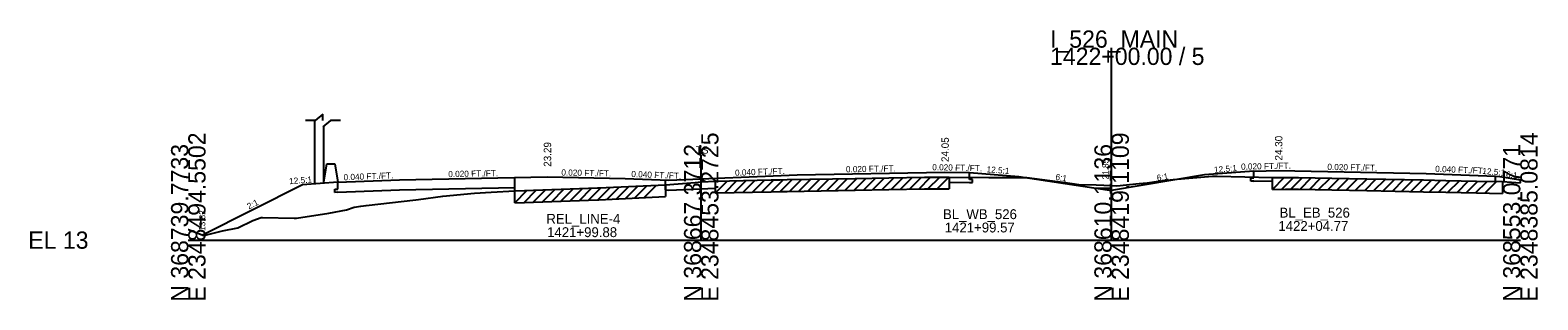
# Model space of a CAD drawing. Extents: x -170 to 2527928, y -10 to 1619750.
# Drawn here: x 3974.3 to 4219.3, y 1990.3 to 2034.1 of the extents above; entities that cross this region are included whole.
import ezdxf

# ---------------------------------------------------------------- set-up
doc = ezdxf.new("R2010")
doc.units = 0
for name, color, linetype in [('Default', 7, 'Continuous'), ('RD_GPK_XS_Cell', 7, 'Continuous'), ('RD_PD_NOISE-WALL-GM', 7, 'Continuous'), ('RD_XS_Base', 7, 'Continuous'), ('RD_XS_EarthShd', 7, 'Continuous'), ('RD_XS_ExGround', 7, 'Continuous'), ('RD_XS_ExPaveRet', 7, 'Continuous'), ('RD_XS_MatchLine', 7, 'Continuous'), ('RD_XS_Pave', 7, 'Continuous'), ('RD_XS_PaveShd', 7, 'Continuous'), ('RD_XS_TieSlope', 7, 'Continuous'), ('RD_XS_TX_Elev_EX', 7, 'Continuous'), ('RD_XS_TX_Slope', 7, 'Continuous'), ('RD_XS_TX_Station', 7, 'Continuous')]:
    doc.layers.add(name, color=color, linetype=linetype)

msp = doc.modelspace()

# ---------------------------------------------------------------- linework, layer by layer
at = {"layer": 'Default'}
for p, q in [((4020.63, 2019.42), (4019.05, 2019.42)), ((4021.88, 2020.45), (4020.63, 2019.42)), ((4021.88, 2019.42), (4021.88, 2020.45)), ((4023.13, 2019.42), (4021.88, 2018.4)), ((4024.73, 2019.42), (4023.13, 2019.42))]:
    msp.add_line(p, q, dxfattribs=at)
at = {"layer": 'RD_GPK_XS_Cell'}
for p, q in [((4150.02, 2000), (4150.02, 2031.24)), ((4000, 2000), (4083.34, 2000)), ((4083.34, 2000), (4150.02, 2000)), ((4150.02, 2000), (4216.43, 2000))]:
    msp.add_line(p, q, dxfattribs=at)
at = {"layer": 'RD_PD_NOISE-WALL-GM'}
for p, q in [((4020.5, 2019.42), (4020.5, 2009.1)), ((4022, 2009.22), (4022, 2018.5)), ((4022, 2009.41), (4022.49, 2012.41)), ((4022.49, 2012.41), (4023.82, 2012.41)), ((4023.82, 2012.41), (4024.31, 2009.41))]:
    msp.add_line(p, q, dxfattribs=at)
at = {"layer": 'RD_XS_Base'}
for p, q in [((4173.12, 2010.09), (4173.12, 2011.22)), ((4024.31, 2008.27), (4024.31, 2009.41)), ((4053.05, 2008), (4053.05, 2010.18)), ((4077.53, 2008.14), (4077.53, 2009.77)), ((4123.63, 2009.4), (4126.92, 2009.34)), ((4126.92, 2009.84), (4126.92, 2010.97)), ((4127.42, 2009.83), (4126.92, 2009.84)), ((4126.92, 2009.34), (4127.42, 2009.33)), ((4127.42, 2009.33), (4127.42, 2009.83)), ((4172.62, 2010.08), (4173.12, 2010.09)), ((4172.62, 2009.58), (4172.62, 2010.08)), ((4173.12, 2009.59), (4172.62, 2009.58)), ((4173.12, 2009.59), (4176.15, 2009.65)), ((4212.37, 2009.52), (4212.37, 2010.38)), ((4023.81, 2008.25), (4024.31, 2008.27)), ((4023.81, 2007.75), (4023.81, 2008.25)), ((4024.31, 2007.77), (4023.81, 2007.75)), ((4024.31, 2007.77), (4034.31, 2008.17)), ((4034.31, 2008.17), (4053.05, 2008.55)), ((4077.53, 2008.14), (4078.09, 2008.12)), ((4078.09, 2008.12), (4085.68, 2008.42))]:
    msp.add_line(p, q, dxfattribs=at)
at = {"layer": 'RD_XS_EarthShd'}
for p, q in [((4173.12, 2011.22), (4165.12, 2010.58)), ((4018.54, 2008.95), (4002.3, 2000.82)), ((4024.31, 2009.41), (4018.54, 2008.95)), ((4126.92, 2010.97), (4134.92, 2010.33))]:
    msp.add_line(p, q, dxfattribs=at)
at = {"layer": 'RD_XS_ExGround'}
msp.add_lwpolyline([(4000, 2001.75), (4000.04, 2001.74), (4002.52, 2000.74), (4005.56, 2001.5), (4008.03, 2001.99), (4010.48, 2003.18), (4011.82, 2003.65), (4012.08, 2003.65), (4017.23, 2003.54), (4017.31, 2003.55), (4017.58, 2003.58), (4022.84, 2004.39), (4025.69, 2004.93), (4026.96, 2005.35), (4028.05, 2005.5), (4028.92, 2005.61), (4036.95, 2006.53), (4037.4, 2006.57), (4041.36, 2007.13), (4046.51, 2007.6), (4049.21, 2007.77), (4053.05, 2008), (4054.64, 2008.04), (4065, 2008.42), (4066.5, 2008.47), (4066.68, 2008.48), (4077.53, 2008.99), (4082.33, 2009.38), (4083.34, 2009.44), (4085.68, 2009.58), (4094.7, 2009.77), (4096.16, 2009.8), (4097.31, 2009.82), (4108.34, 2010.02), (4113.82, 2010.12), (4119.62, 2010.22), (4121.45, 2010.22), (4123.63, 2010.21), (4130.08, 2010.17), (4136.22, 2010.15), (4142.45, 2009.34), (4143.59, 2009.2), (4144.7, 2009.05), (4147.53, 2008.95), (4150.02, 2008.85), (4150.87, 2008.82), (4154.52, 2009.17), (4155.81, 2009.31), (4157.65, 2009.55), (4160, 2009.83), (4166.43, 2010.41), (4167.16, 2010.4), (4176.15, 2010.16), (4178.29, 2010.18), (4180.36, 2010.19), (4185.8, 2010.07), (4191.49, 2009.97), (4200.7, 2009.78), (4204.31, 2009.7), (4209.32, 2009.57), (4213.53, 2009.5), (4216.43, 2009.3)], dxfattribs=at)
at = {"layer": 'RD_XS_ExPaveRet'}
for p, q in [((4071.05, 2006.77), (4073.06, 2008.78)), ((4072.55, 2006.84), (4074.56, 2008.85)), ((4074.05, 2006.91), (4076.06, 2008.92)), ((4077.53, 2008.99), (4077.53, 2007.07)), ((4085.68, 2007.67), (4087.63, 2009.62)), ((4085.68, 2007.67), (4085.68, 2009.58)), ((4087.18, 2007.7), (4089.13, 2009.66)), ((4088.68, 2007.73), (4090.63, 2009.69)), ((4090.18, 2007.76), (4092.13, 2009.72)), ((4091.68, 2007.79), (4093.63, 2009.75)), ((4093.18, 2007.82), (4095.13, 2009.78)), ((4094.68, 2007.85), (4096.63, 2009.81)), ((4096.18, 2007.89), (4098.13, 2009.84)), ((4097.68, 2007.91), (4099.63, 2009.86)), ((4099.18, 2007.94), (4101.13, 2009.89)), ((4100.68, 2007.97), (4102.63, 2009.92)), ((4102.18, 2007.99), (4104.13, 2009.94)), ((4103.68, 2008.02), (4105.63, 2009.97)), ((4105.18, 2008.05), (4107.13, 2010)), ((4106.68, 2008.07), (4108.63, 2010.02)), ((4108.18, 2008.1), (4110.13, 2010.05)), ((4109.68, 2008.13), (4111.63, 2010.08)), ((4111.18, 2008.15), (4113.13, 2010.1)), ((4112.68, 2008.18), (4114.63, 2010.13)), ((4114.18, 2008.21), (4116.13, 2010.16)), ((4115.68, 2008.23), (4117.63, 2010.19)), ((4117.18, 2008.26), (4119.13, 2010.21)), ((4118.68, 2008.29), (4120.61, 2010.22)), ((4120.18, 2008.31), (4122.09, 2010.22)), ((4121.68, 2008.3), (4123.59, 2010.21)), ((4123.63, 2010.21), (4123.63, 2008.3)), ((4176.15, 2008.24), (4178.08, 2010.18)), ((4176.15, 2008.24), (4176.15, 2010.16)), ((4177.65, 2008.26), (4179.58, 2010.18)), ((4179.15, 2008.27), (4181.05, 2010.17)), ((4180.65, 2008.27), (4182.52, 2010.14)), ((4182.15, 2008.23), (4184.02, 2010.11)), ((4183.65, 2008.2), (4185.52, 2010.08)), ((4185.15, 2008.17), (4187.03, 2010.05)), ((4186.65, 2008.14), (4188.53, 2010.02)), ((4188.15, 2008.11), (4190.03, 2010)), ((4189.65, 2008.09), (4191.53, 2009.97)), ((4191.15, 2008.06), (4193.02, 2009.94)), ((4192.65, 2008.03), (4194.52, 2009.91)), ((4194.15, 2008), (4196.02, 2009.87)), ((4195.65, 2007.97), (4197.52, 2009.84)), ((4197.15, 2007.93), (4199.02, 2009.81)), ((4198.65, 2007.9), (4200.52, 2009.78)), ((4200.15, 2007.87), (4202.02, 2009.75)), ((4201.65, 2007.84), (4203.52, 2009.71)), ((4203.15, 2007.8), (4205.02, 2009.68)), ((4204.65, 2007.77), (4206.52, 2009.64)), ((4206.15, 2007.73), (4208.02, 2009.61)), ((4207.65, 2007.7), (4209.52, 2009.57)), ((4209.15, 2007.66), (4211.03, 2009.54)), ((4210.65, 2007.63), (4212.53, 2009.52)), ((4213.53, 2009.5), (4213.53, 2007.58)), ((4053.05, 2006.08), (4055.02, 2008.06)), ((4053.05, 2006.08), (4053.05, 2008)), ((4054.55, 2006.12), (4056.54, 2008.11)), ((4054.64, 2006.13), (4065, 2006.5)), ((4056.05, 2006.18), (4058.04, 2008.17)), ((4057.55, 2006.23), (4059.54, 2008.22)), ((4059.05, 2006.29), (4061.04, 2008.27)), ((4060.55, 2006.34), (4062.54, 2008.33)), ((4062.05, 2006.39), (4064.04, 2008.38)), ((4063.55, 2006.45), (4065.54, 2008.44)), ((4065, 2006.5), (4066.5, 2006.55)), ((4065.05, 2006.5), (4067.04, 2008.5)), ((4066.5, 2006.55), (4066.68, 2006.56)), ((4066.55, 2006.56), (4068.56, 2008.57)), ((4066.68, 2006.56), (4077.53, 2007.07)), ((4068.05, 2006.63), (4070.06, 2008.64)), ((4069.55, 2006.7), (4071.56, 2008.71)), ((4085.68, 2007.67), (4094.7, 2007.85)), ((4094.7, 2007.85), (4096.16, 2007.88)), ((4096.16, 2007.88), (4097.31, 2007.91)), ((4097.31, 2007.91), (4108.34, 2008.1)), ((4108.34, 2008.1), (4113.82, 2008.2)), ((4113.82, 2008.2), (4119.62, 2008.31)), ((4119.62, 2008.31), (4121.45, 2008.3)), ((4121.45, 2008.3), (4123.63, 2008.3)), ((4176.15, 2008.24), (4178.29, 2008.26)), ((4178.29, 2008.26), (4180.36, 2008.27)), ((4180.36, 2008.27), (4185.8, 2008.16)), ((4185.8, 2008.16), (4191.49, 2008.05)), ((4191.49, 2008.05), (4200.7, 2007.86)), ((4200.7, 2007.86), (4204.31, 2007.78)), ((4204.31, 2007.78), (4209.32, 2007.66)), ((4209.32, 2007.66), (4213.53, 2007.58)), ((4053.05, 2006.08), (4054.64, 2006.13))]:
    msp.add_line(p, q, dxfattribs=at)
at = {"layer": 'RD_XS_MatchLine'}
msp.add_line((4083.34, 2000), (4083.34, 2013.78), dxfattribs=at)
at = {"layer": 'RD_XS_Pave'}
for p, q in [((4177.12, 2011.3), (4201.12, 2010.83)), ((4034.31, 2009.81), (4058.31, 2010.29)), ((4058.31, 2010.29), (4071.01, 2010.03)), ((4098.91, 2010.58), (4122.92, 2011.05))]:
    msp.add_line(p, q, dxfattribs=at)
at = {"layer": 'RD_XS_PaveShd'}
for p, q in [((4173.12, 2011.22), (4177.12, 2011.3)), ((4024.31, 2009.41), (4034.31, 2009.81)), ((4071.01, 2010.03), (4078.09, 2009.75)), ((4078.09, 2009.75), (4098.91, 2010.58)), ((4122.92, 2011.05), (4126.92, 2010.97)), ((4201.12, 2010.83), (4212.37, 2010.38))]:
    msp.add_line(p, q, dxfattribs=at)
at = {"layer": 'RD_XS_TieSlope'}
for p, q in [((4134.92, 2010.33), (4150.02, 2008.07)), ((4165.12, 2010.58), (4150.02, 2008.07)), ((4212.37, 2010.38), (4213.12, 2010.32)), ((4213.12, 2010.32), (4216.43, 2009.77)), ((4216.43, 2009.3), (4216.43, 2009.77))]:
    msp.add_line(p, q, dxfattribs=at)

# ---------------------------------------------------------------- texts
at = {"layer": 'RD_GPK_XS_Cell'}
for s, p in [('I_526_MAIN', (4140.02, 2031.24)), ('1422+00.00 / 5', (4140.02, 2028.44)), ('EL 13', (3974, 1998.6))]:
    msp.add_text(s, height=2.8, dxfattribs=at).set_placement(p)
for s, p in [('E 2348494.5502', (4002.8, 1990)), ('E 2348453.2725', (4086.14, 1990)), ('E 2348419.1109', (4152.82, 1990)), ('E 2348385.0814', (4219.23, 1990)), ('N 368739.7733', (4000, 1990)), ('N 368667.3712', (4083.34, 1990)), ('N 368610.1136', (4150.02, 1990)), ('N 368553.0771', (4216.43, 1990))]:
    msp.add_text(s, height=2.8, rotation=90, dxfattribs=at).set_placement(p)
at = {"layer": 'RD_XS_MatchLine'}
msp.add_text('TS', height=1.2, dxfattribs=at).set_placement((4082.48, 2014.03))
at = {"layer": 'RD_XS_TX_Elev_EX'}
msp.add_text('21.85', height=1, rotation=90, dxfattribs=at).set_placement((4149.52, 2009.85))
at = {"layer": 'RD_XS_TX_Slope'}
for s, rotation, p in [('0.020 FT./FT.', 1.1458, (4042.25, 2010.22)), ('0.020 FT./FT.', 358.8542, (4060.61, 2010.49)), ('0.040 FT./FT.', 357.7094, (4071.97, 2010.25)), ('0.040 FT./FT.', 2.2782, (4088.85, 2010.43)), ('0.020 FT./FT.', 1.1334, (4106.86, 2010.99)), ('0.020 FT./FT.', 358.8421, (4120.87, 2011.35)), ('12.5:1', 355.4261, (4129.67, 2011.01)), ('12.5:1', 4.5739, (4166.7, 2010.92)), ('0.020 FT./FT.', 1.1572, (4171.06, 2011.43)), ('0.020 FT./FT.', 358.8659, (4185.07, 2011.4)), ('0.040 FT./FT.', 357.7094, (4202.58, 2011.08)), ('12.5:1', 355.4261, (4210.23, 2010.74)), ('6:1', 352.6182, (4214.05, 2010.21)), ('12.5:1', 4.5739, (4016.43, 2009.07)), ('0.040 FT./FT.', 2.2906, (4025.25, 2009.7)), ('6:1', 350.5377, (4140.84, 2009.8)), ('6:1', 9.4623, (4157.45, 2009.59)), ('2:1', 26.5651, (4009.85, 2004.96)), ('13.82', 90, (4002.76, 2001.5))]:
    msp.add_text(s, height=1, rotation=rotation, dxfattribs=at).set_placement(p)
at = {"layer": 'RD_XS_TX_Station'}
for s, p in [(' 24.05', (4123.57, 2012.23)), (' 24.30', (4177.77, 2012.48)), (' 23.29', (4058.96, 2011.46))]:
    msp.add_text(s, height=1.2, rotation=90, dxfattribs=at).set_placement(p)
for s, p in [('REL_LINE-4', (4058.18, 2002.66)), ('BL_WB_526', (4122.62, 2003.41)), ('BL_EB_526', (4177.31, 2003.66)), ('1421+99.88', (4058.31, 2000.49)), ('1421+99.57', (4122.92, 2001.25)), ('1422+04.77', (4177.12, 2001.5))]:
    msp.add_text(s, height=1.6, dxfattribs=at).set_placement(p)

doc.saveas('drawing.dxf')
